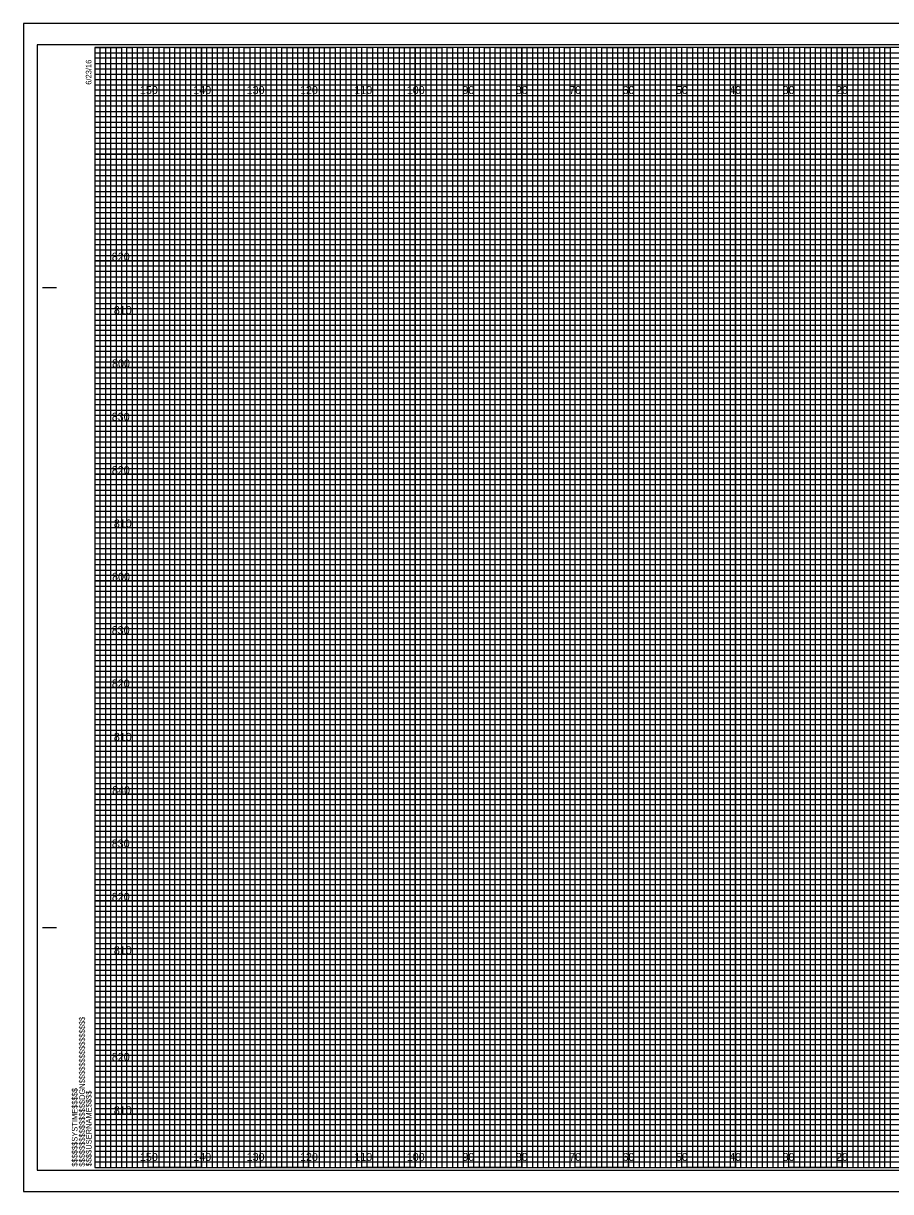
# Model space of a CAD drawing. Extents: x -13 to 323, y -4 to 214.
# Drawn here: x -13.4 to 149.1, y -4.5 to 214.5 of the extents above; entities that cross this region are included whole.
import ezdxf

# ---------------------------------------------------------------- set-up
doc = ezdxf.new("R2010")
doc.units = 0
for name, color, linetype in [('Exist Cross Section Cell', 7, 'Continuous'), ('Exist XS Center Line Elevation Label', 7, 'Continuous'), ('Exist XS Ground Line', 7, 'Continuous'), ('Old_Level_10', 7, 'Continuous'), ('Prop CMT Pvmt Course 2', 7, 'Continuous'), ('Prop CMT Pvmt Course 3', 7, 'Continuous'), ('Prop CMT Pvmt Surface', 7, 'Continuous'), ('Prop CMT Shld Paved Course 1', 7, 'Continuous'), ('Prop CMT Shld Paved Course 3', 7, 'Continuous'), ('Prop CMT Subgrade Earthwork', 7, 'Continuous'), ('Scratch_Level_7', 7, 'Continuous')]:
    doc.layers.add(name, color=color, linetype=linetype)

msp = doc.modelspace()

# ---------------------------------------------------------------- linework, layer by layer
at = {"layer": 'Exist XS Center Line Elevation Label'}
for points in [[(0, 210), (5, 210), (5, 0), (15, 0), (15, 210), (25, 210), (25, 0), (35, 0), (35, 210), (45, 210), (45, 0), (55, 0), (55, 210), (65, 210), (65, 0), (75, 0), (75, 210), (85, 210), (85, 0), (95, 0), (95, 210), (105, 210), (105, 0), (115, 0), (115, 210), (125, 210), (125, 0), (135, 0), (135, 210), (145, 210), (145, 0), (155, 0)], [(0, 205), (275, 205)], [(0, 185), (320, 185), (320, 195), (0, 195)], [(0, 165), (320, 165), (320, 175), (0, 175)], [(0, 145), (320, 145), (320, 155), (0, 155)], [(0, 125), (320, 125), (320, 135), (0, 135)], [(0, 105), (320, 105), (320, 115), (0, 115)], [(0, 85), (320, 85), (320, 95), (0, 95)], [(0, 65), (320, 65), (320, 75), (0, 75)], [(0, 45), (320, 45), (320, 55), (0, 55)], [(0, 25), (320, 25), (320, 35), (0, 35)], [(0, 5), (320, 5), (320, 15), (0, 15)]]:
    msp.add_lwpolyline(points, dxfattribs=at)
at = {"layer": 'Exist XS Ground Line'}
for p, q in [((10, 210), (0, 210)), ((10, 0), (10, 210)), ((30, 210), (20, 210)), ((20, 210), (20, 0)), ((30, 0), (30, 210)), ((50, 210), (40, 210)), ((40, 210), (40, 0)), ((50, 0), (50, 210)), ((70, 210), (60, 210)), ((60, 210), (60, 0)), ((70, 0), (70, 210)), ((90, 210), (80, 210)), ((80, 210), (80, 0)), ((90, 0), (90, 210)), ((110, 210), (100, 210)), ((100, 210), (100, 0)), ((110, 0), (110, 210)), ((130, 210), (120, 210)), ((120, 210), (120, 0)), ((130, 0), (130, 210)), ((150, 210), (140, 210)), ((140, 210), (140, 0)), ((20, 0), (10, 0)), ((40, 0), (30, 0)), ((60, 0), (50, 0)), ((80, 0), (70, 0)), ((100, 0), (90, 0)), ((120, 0), (110, 0)), ((140, 0), (130, 0))]:
    msp.add_line(p, q, dxfattribs=at)
for points in [[(0, 200), (320, 200), (320, 190), (0, 190)], [(0, 180), (320, 180), (320, 170), (0, 170)], [(0, 160), (320, 160), (320, 150), (0, 150)], [(0, 140), (320, 140), (320, 130), (0, 130)], [(0, 120), (320, 120), (320, 110), (0, 110)], [(0, 100), (320, 100), (320, 90), (0, 90)], [(0, 80), (320, 80), (320, 70), (0, 70)], [(0, 60), (320, 60), (320, 50), (0, 50)], [(0, 40), (320, 40), (320, 30), (0, 30)], [(0, 20), (320, 20), (320, 10), (0, 10)]]:
    msp.add_lwpolyline(points, dxfattribs=at)
at = {"layer": 'Old_Level_10'}
for p, q in [((0, 209), (260, 209)), ((260, 207.98), (0, 207.98)), ((0, 207.98), (0, 207)), ((0, 207), (260, 207)), ((260, 205.89), (0, 205.89)), ((0, 205.89), (0, 204)), ((0, 204), (320, 204))]:
    msp.add_line(p, q, dxfattribs=at)
for points in [[(0, 203), (270, 203), (320, 203), (320, 202), (0, 202)], [(0, 201), (320, 201), (320, 199), (0, 199)], [(0, 198), (320, 198), (320, 197), (0, 196.98)], [(0, 196), (320, 196), (320, 194), (0, 194)], [(0, 193), (320, 193), (320, 192), (0, 192)], [(0, 191), (320, 191), (320, 189), (0, 189)], [(0, 188), (320, 188), (320, 187), (0, 187)], [(0, 186), (320, 186), (320, 184), (0, 184)], [(0, 183), (320, 183), (320, 182), (0, 182)], [(0, 181), (320, 181), (320, 179), (0, 179)], [(0, 178), (320, 178), (320, 177), (0, 177)], [(0, 176), (320, 176), (320, 173.95), (320, 173), (320, 172), (0, 172)], [(0, 174), (320, 174), (320, 173), (0, 173)], [(0, 171), (320, 171), (320, 169), (0, 169.03)], [(0, 169.03), (320, 169), (320, 168), (0, 168)], [(0, 167), (320, 167), (320, 166), (0, 166)], [(0, 164), (320, 164), (320, 163), (0, 163)], [(0, 162), (320, 162), (320, 161), (0, 161)], [(-0.07, 158.89), (320, 158.89), (320, 157.88), (-0.07, 157.88)], [(0, 157), (320, 157), (320, 156), (0, 156)], [(0, 154), (320, 154), (320, 153), (0, 153)], [(0, 152), (320, 152), (320, 151), (0, 151)], [(0, 149), (320, 149), (320, 148), (0, 148)], [(0, 147), (320, 147), (320, 146), (0, 146)], [(0, 144), (320, 144), (320, 143), (0, 143)], [(0, 142), (320, 142), (320, 141), (0, 141)], [(0, 139), (320, 139), (319.99, 137.98), (0, 138)], [(0, 137), (320, 137), (320, 136), (0, 136)], [(0, 134), (320, 134), (320, 133), (0, 133)], [(0, 132), (320, 132), (320, 131), (0, 131)], [(0, 129), (320, 129), (320, 128), (0, 128)], [(0, 127), (320, 127), (320, 126), (0, 126)], [(0, 124), (320, 124), (320, 123), (0, 123)], [(0, 122), (320, 122), (320, 121), (0, 121)], [(0, 119), (320, 119), (320, 118), (0, 118)], [(0, 116.99), (320.07, 116.91), (320, 116), (0, 116)], [(0, 114), (320, 114), (320, 113), (0, 113)], [(0, 112), (320, 112), (320, 111), (0, 111)], [(0, 109), (320, 109), (320, 108), (0, 108)], [(0, 107), (320, 107), (320, 106), (0, 106)], [(0, 104), (320, 104), (320, 103), (0, 103)], [(0, 102), (320, 102), (320, 101), (0, 101)], [(0, 99), (320, 99), (320, 98), (0, 98)], [(0, 97), (320, 97), (320, 96), (0, 96)], [(0, 94), (320, 94), (320, 93), (0, 93)], [(0, 92), (320, 92), (320, 91), (0, 91)], [(0, 89), (320, 89), (320, 88), (0, 88)], [(0, 87), (320, 87), (320, 86), (0, 86)], [(0, 84), (320, 84), (320, 83), (0, 83)], [(0, 82), (320, 82), (320, 81), (0, 81)], [(0, 79), (320, 79), (319.99, 77.98), (0, 78)], [(0, 77), (320, 77), (320, 76), (0, 76)], [(0, 74), (320, 74), (320, 73), (0, 73)], [(0, 72), (320, 72), (320, 71), (0, 71)], [(0, 69), (320, 69), (320, 68), (0, 68)], [(0, 67), (320, 67), (320, 66), (0, 66)], [(0, 64), (320, 64), (320, 63), (0, 63)], [(0, 62), (320, 62), (320, 61), (0, 61)], [(0, 59), (320, 59), (320, 58), (0, 58)], [(0, 56.99), (320.07, 56.91), (320, 56), (0, 56)], [(0, 54), (320, 54), (320, 53), (0, 53)], [(0, 52), (320, 52), (320, 51), (0, 51)], [(0, 49), (320, 49), (320, 48), (0, 48)], [(0, 47), (320, 47), (320, 46), (0, 46)], [(0, 44), (320, 44), (320, 43), (0, 43)], [(0, 42), (320, 42), (320, 41), (0, 41)], [(0, 39), (320, 39), (320, 38), (0, 38)], [(0, 37), (320, 37), (320, 36), (0, 36)], [(0, 34), (320, 34), (320, 33), (0, 33)], [(0, 32), (320, 32), (320, 31), (0, 31)], [(0, 29), (320, 29), (320, 28), (0, 28)], [(0, 27), (320, 27), (320, 26), (0, 26)], [(0, 24), (320, 24), (320, 23), (0, 23)], [(0, 22), (320, 22), (320, 21), (0, 21)], [(0, 19), (320, 19), (320, 18), (0, 18)], [(0, 17), (320, 17), (320, 16), (0, 16)], [(0, 14), (320, 14), (320, 13), (0, 13)], [(0, 12), (320, 12), (320, 11), (0, 11)], [(0, 9), (320, 9), (320, 8), (0, 8)], [(0, 7), (320, 7), (320, 6), (0, 6)], [(0, 4), (320, 4), (320, 3), (0, 3)], [(0, 2), (320, 2), (320, 1), (0, 1)]]:
    msp.add_lwpolyline(points, dxfattribs=at)
at = {"layer": 'Prop CMT Pvmt Course 2'}
msp.add_lwpolyline([(-10.8, -0.5), (322.4, -0.5), (322.4, 210.5), (-10.8, 210.5)], close=True, dxfattribs=at)
at = {"layer": 'Prop CMT Pvmt Course 3'}
for p, q in [((10, 0), (10, 210)), ((20, 0), (20, 210)), ((30, 0), (30, 210)), ((40, 0), (40, 210)), ((50, 0), (50, 210)), ((60, 0), (60, 210)), ((70, 0), (70, 210)), ((80, 0), (80, 210)), ((90, 0), (90, 210)), ((100, 0), (100, 210)), ((110, 0), (110, 210)), ((120, 0), (120, 210)), ((130, 0), (130, 210)), ((140, 0), (140, 210)), ((0, 200), (320, 200)), ((0, 190), (320, 190)), ((0, 180), (320, 180)), ((0, 170), (320, 170)), ((0, 160), (320, 160)), ((0, 150), (320, 150)), ((0, 140), (320, 140)), ((0, 130), (320, 130)), ((0, 120), (320, 120)), ((0, 110), (320, 110)), ((0, 100), (320, 100)), ((0, 90), (320, 90)), ((0, 80), (320, 80)), ((0, 70), (320, 70)), ((0, 60), (320, 60)), ((0, 50), (320, 50)), ((0, 40), (320, 40)), ((0, 30), (320, 30)), ((0, 20), (320, 20)), ((0, 10), (320, 10))]:
    msp.add_line(p, q, dxfattribs=at)
at = {"layer": 'Prop CMT Shld Paved Course 1'}
for p, q in [((-9.8, 165), (-7.3, 165)), ((-9.7, 165), (-7.2, 165)), ((-9.8, 45), (-7.3, 45)), ((-9.7, 45), (-7.2, 45)), ((0, 0), (0, 0)), ((0, 0), (0, 0)), ((0, 0), (0, 0)), ((0, 0), (0, 0)), ((0, 0), (0, 0)), ((0, 0), (0, 0)), ((0, 0), (0, 0))]:
    msp.add_line(p, q, dxfattribs=at)
msp.add_lwpolyline([(320, 210), (0, 210), (0, 0), (320, 0)], close=True, dxfattribs=at)
at = {"layer": 'Prop CMT Shld Paved Course 3'}
msp.add_lwpolyline([(-13.4, -4.5), (323.3, -4.5), (323.3, 214.5), (-13.4, 214.5)], close=True, dxfattribs=at)
at = {"layer": 'Prop CMT Subgrade Earthwork'}
for p, q in [((323.3, 214.5), (-13.4, 214.5)), ((-13.4, 214.5), (-13.4, -4.5)), ((-13.4, -4.5), (323.3, -4.5))]:
    msp.add_line(p, q, dxfattribs=at)
at = {"layer": 'Scratch_Level_7'}
for points in [[(0, 0), (1, 0), (1, 210), (2, 210), (2, 0)], [(2, 0), (3, 0), (3, 210), (4, 210), (4, 0)], [(5, 0), (6, 0), (6, 210), (7, 210), (7, 0)], [(7, 0), (8, 0), (8, 210), (9, 210), (9, 0)], [(10, 0), (11, 0), (11, 210), (12, 210), (12, 0)], [(12, 0), (13, 0), (13, 210), (14, 210), (14, 0)], [(15, 0), (16, 0), (16, 210), (17, 210), (17, 0)], [(17, 0), (18, 0), (18, 210), (19, 210), (19, 0)], [(20, 0), (21, 0), (21, 210), (22, 210), (22, 0)], [(22, 0), (23, 0), (23, 210), (24, 210), (24, 0)], [(25, 0), (26, 0), (26, 210), (27, 210), (27, 0)], [(27, 0), (28, 0), (28, 210), (29, 210), (29, 0)], [(30, 0), (31, 0), (31, 210), (32, 210), (32, 0)], [(32, 0), (33, 0), (33, 210), (34, 210), (34, 0)], [(35, 0), (36, 0), (36, 210), (37, 210), (37, 0)], [(37, 0), (38, 0), (38, 210), (39, 210), (39, 0)], [(40, 0), (41, 0), (41, 210), (42, 210), (42, 0)], [(42, 0), (43, 0), (43, 210), (44, 210), (44, 0)], [(45, 0), (46, 0), (46, 210), (47, 210), (47, 0)], [(47, 0), (48, 0), (48, 210), (49, 210), (49, 0)], [(50, 0), (51, 0), (51, 210), (52, 210), (52, 0)], [(52, 0), (53, 0), (53, 210), (54, 210), (54, 0)], [(55, 0), (56, 0), (56, 210), (57, 210), (57, 0)], [(57, 0), (58, 0), (58, 210), (59, 210), (59, 0)], [(60, 0), (61, 0), (61, 210), (62, 210), (62, 0)], [(62, 0), (63, 0), (63, 210), (64, 210), (64, 0)], [(65, 0), (66, 0), (66, 210), (67, 210), (67, 0)], [(67, 0), (68, 0), (68, 210), (69, 210), (69, 0)], [(70, 0), (71, 0), (71, 210), (72, 210), (72, 0)], [(72, 0), (73, 0), (73, 210), (74, 210), (74, 0)], [(75, 0), (76, 0), (76, 210), (77, 210), (77, 0)], [(77, 0), (78, 0), (78, 210), (79, 210), (79, 0)], [(80, 0), (81, 0), (81, 210), (82, 210), (82, 0)], [(82, 0), (83, 0), (83, 210), (84, 210), (84, 0)], [(85, 0), (86, 0), (86, 210), (87, 210), (87, 0)], [(87, 0), (88, 0), (88, 210), (89, 210), (89, 0)], [(90, 0), (91, 0), (91, 210), (92, 210), (92, 0)], [(92, 0), (93, 0), (93, 210), (94, 210), (94, 0)], [(95, 0), (96, 0), (96, 210), (97, 210), (97, 0)], [(97, 0), (98, 0), (98, 210), (99, 210), (99, 0)], [(100, 0), (101, 0), (101, 210), (102, 210), (102, 0)], [(102, 0), (103, 0), (103, 210), (104, 210), (104, 0)], [(105, 0), (106, 0), (106, 210), (107, 210), (107, 0)], [(107, 0), (108, 0), (108, 210), (109, 210), (109, 0)], [(110, 0), (111, 0), (111, 210), (112, 210), (112, 0)], [(112, 0), (113, 0), (113, 210), (114, 210), (114, 0)], [(115, 0), (116, 0), (116, 210), (117, 210), (117, 0)], [(117, 0), (118, 0), (118, 210), (119, 210), (119, 0)], [(120, 0), (121, 0), (121, 210), (122, 210), (122, 0)], [(122, 0), (123, 0), (123, 210), (124, 210), (124, 0)], [(125, 0), (126, 0), (126, 210), (127, 210), (127, 0)], [(127, 0), (128, 0), (128, 210), (129, 210), (129, 0)], [(130, 0), (131, 0), (131, 210), (132, 210), (132, 0)], [(132, 0), (133, 0), (133, 210), (134, 210), (134, 0)], [(135, 0), (136, 0), (136, 210), (137, 210), (137, 0)], [(137, 0), (138, 0), (138, 210), (139, 210), (139, 0)], [(140, 0), (141, 0), (141, 210), (142, 210), (142, 0)], [(142, 0), (143, 0), (143, 210), (144, 210), (144, 0)], [(145, 0), (146, 0), (146, 210), (147, 210), (147, 0)], [(147, 0), (148, 0), (148, 210), (149, 210), (149, 0)]]:
    msp.add_lwpolyline(points, dxfattribs=at)

# ---------------------------------------------------------------- texts
at = {"layer": 'Exist Cross Section Cell'}
for s, p in [('150', (8.44, 201.25)), ('140', (18.44, 201.25)), ('130', (28.44, 201.25)), ('120', (38.44, 201.25)), ('110', (48.62, 201.25)), ('100', (58.44, 201.25)), ('90', (68.86, 201.25)), ('80', (78.86, 201.25)), ('70', (88.86, 201.25)), ('60', (98.86, 201.25)), ('50', (108.86, 201.25)), ('40', (118.86, 201.25)), ('30', (128.86, 201.25)), ('20', (138.86, 201.25)), ('150', (8.44, 1.25)), ('140', (18.44, 1.25)), ('130', (28.44, 1.25)), ('120', (38.44, 1.25)), ('110', (48.62, 1.25)), ('100', (58.44, 1.25)), ('90', (68.86, 1.25)), ('80', (78.86, 1.25)), ('70', (88.86, 1.25)), ('60', (98.86, 1.25)), ('50', (108.86, 1.25)), ('40', (118.86, 1.25)), ('30', (128.86, 1.25)), ('20', (138.86, 1.25))]:
    msp.add_text(s, height=1.5, dxfattribs=at).set_placement(p)
at = {"layer": 'Prop CMT Pvmt Surface'}
for s, p in [('820', (3.17, 170)), ('810', (3.55, 160)), ('800', (3.22, 150)), ('830', (3.16, 140)), ('820', (3.17, 130)), ('810', (3.55, 120)), ('800', (3.22, 110)), ('830', (3.16, 100)), ('820', (3.17, 90)), ('810', (3.55, 80)), ('840', (3.24, 70)), ('830', (3.16, 60)), ('820', (3.17, 50)), ('810', (3.55, 40)), ('820', (3.17, 20)), ('810', (3.55, 10))]:
    msp.add_text(s, height=1.5, dxfattribs=at).set_placement(p)
at = {"layer": 'Prop CMT Shld Paved Course 1'}
for s, p in [('6/23/16', (-0.65, 203)), ('$$$$$$$$$$$$$$$$DGN$$$$$$$$$$$$$$$$', (-1.88, 0.18)), ('$$$$$$SYSTIME$$$$$', (-3.26, 0.18)), ('$$$$USERNAME$$$$', (-0.62, 0.23))]:
    msp.add_text(s, height=1.05, rotation=90, dxfattribs=at).set_placement(p)

doc.saveas('drawing.dxf')
